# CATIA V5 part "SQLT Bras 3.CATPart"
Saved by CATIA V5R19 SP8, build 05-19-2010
Part number: SQLT Bras 3
Publications: "Droite.1", "Droite.2", "Droite.3", "Plan.1"
Bounding box of the stored display mesh (mm): x -1000 to 1000, y 1200 to 2700, z -750 to 600
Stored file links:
  C:\Users\ThinkMotion\Desktop\EU_thinkMotion\iao\IAO_MMS_Groupe3\fovide\fovide\SQLT Bras 3.CATPart
  C:\Users\ThinkMotion\Desktop\EU_thinkMotion\iao\IAO_MMS_Groupe3\fovide\fovide\fovide.CATProduct
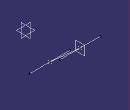
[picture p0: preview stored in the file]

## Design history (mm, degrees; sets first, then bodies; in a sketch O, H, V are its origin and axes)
Set1
  Point1 "Point.A": linked copy from another document
  Point2 "Point.B": linked copy from another document
Set2 "set bras 3"
  Line1: type PtPt, FirstPoint Point1, SecondPoint Point2
  Line2: type Normal, RefPoint Point1, RefSkin yz-plane, Start -1000, End 1000
  Line3: type Normal, RefPoint Point2, RefSkin yz-plane, Start -1000, End 1000
  Plane1: type OffsetPt, RefPlane yz-plane, RefPoint Point1
Body1 (main body)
